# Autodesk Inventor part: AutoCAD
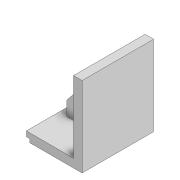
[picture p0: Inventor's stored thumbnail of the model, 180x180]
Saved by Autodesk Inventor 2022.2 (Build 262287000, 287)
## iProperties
Created: 2021-12
Part Number: AutoCAD
Material: 一般
Document SubType Name: Modeling
Designer: taeku
Density: 1 g/cm^3
Appearance: 既定
Author: taeku
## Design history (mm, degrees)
node "AutoCAD.dwg"
sketch "スケッチ1"
  geometry: L1 (249.261, 9)-(237.261, 9) reference; L2 (237.261, 9)-(237.261, 109) reference; L3 (237.261, 109)-(249.261, 109) reference; L4 (249.261, 109)-(249.261, 9) reference; 1 further point
extrude "押し出し1" new body sketch "スケッチ1" stored distance "d0" = 100; taper "d1" = 0 deg
sketch "スケッチ2"
  geometry: L1 (171.261, 2)-(171.261, 9) reference; L2 (171.261, 9)-(249.261, 9) reference; L3 (249.261, 9)-(249.261, -3) reference; L4 (249.261, -3)-(176.261, -3) reference; L5 (176.261, 2)-(171.261, 2) reference; L6 (176.261, -3)-(176.261, 2) reference; 1 further point
extrude "押し出し2" join sketch "スケッチ2" stored distance "d2" = 100; taper "d3" = 0 deg
sketch "スケッチ3"
  geometry: L1 (237.261, 79)-(222.261, 79) reference; L2 (222.261, 79)-(182.261, 29) reference; L3 (182.261, 9)-(182.261, 29) reference; L4 (227.261, 9)-(237.261, 19) reference; L5 (237.261, 79)-(222.261, 79) reference; L6 (237.261, 79)-(237.261, 19); L7 (237.261, 9)-(237.261, 109) reference; L8 (171.261, 9)-(249.261, 9) reference; L9 (227.261, 9)-(182.261, 9); 1 further point
  constraints: 4 end point, 1 collinear, 1 point on line
extrude "押し出し3" join sketch "スケッチ3" stored distance "d4" = 9; taper "d5" = 0 deg
node "ソリッド1"
